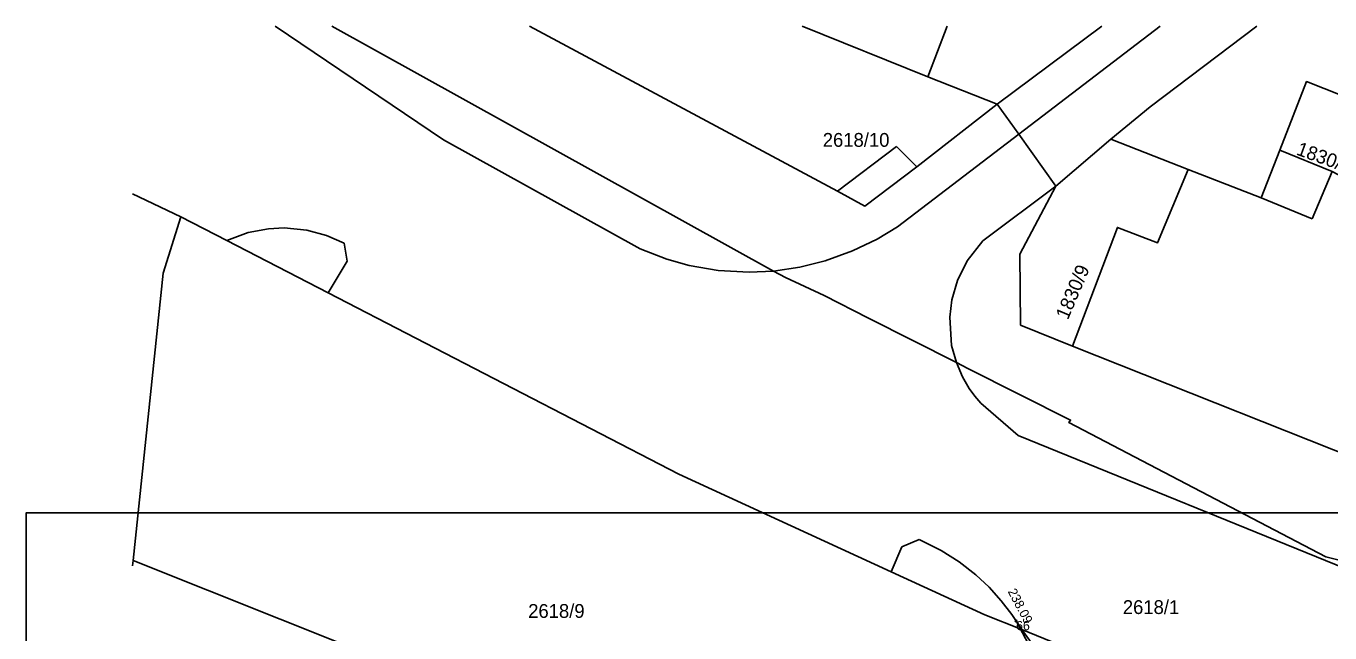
# Model space of a CAD drawing. Extents: x -596309 to -596099, y -1158697 to -1158513.
# Drawn here: x -596309.1 to -596238.2, y -1158545.7 to -1158512.7 of the extents above; entities that cross this region are included whole.
import ezdxf

# ---------------------------------------------------------------- set-up
doc = ezdxf.new("R2010")
doc.units = 0
for name, color, linetype in [('Vrstva 1', 7, 'Continuous'), ('Vrstva 10', 7, 'Continuous'), ('Vrstva 14', 7, 'Continuous'), ('Vrstva 2', 7, 'Continuous'), ('Vrstva 3', 7, 'Continuous'), ('Vrstva 59', 7, 'Continuous'), ('Vrstva 63', 7, 'Continuous')]:
    doc.layers.add(name, color=color, linetype=linetype)

msp = doc.modelspace()

# ---------------------------------------------------------------- linework, layer by layer
at = {"layer": 'Vrstva 1'}
for p, q in [((-596286.36, -1158518.91), (-596295.51, -1158512.73)), ((-596281.683, -1158512.73), (-596264.94, -1158521.71)), ((-596258.974, -1158512.73), (-596260.03, -1158515.48)), ((-596250.58, -1158512.73), (-596256.27, -1158516.97)), ((-596255.09, -1158518.61), (-596247.391, -1158512.73)), ((-596260.63, -1158520.37), (-596256.27, -1158516.97)), ((-596275.68, -1158524.84), (-596286.36, -1158518.91)), ((-596261.68, -1158523.64), (-596255.09, -1158518.61)), ((-596253.07, -1158521.43), (-596250.09, -1158518.88)), ((-596250.09, -1158518.88), (-596245.87, -1158520.53)), ((-596264.94, -1158521.71), (-596261.73, -1158519.27)), ((-596261.73, -1158519.27), (-596260.63, -1158520.37)), ((-596239.14, -1158523.21), (-596238.05, -1158520.63)), ((-596257.04, -1158524.4), (-596253.07, -1158521.43)), ((-596241.91, -1158522.07), (-596239.14, -1158523.21)), ((-596300.64, -1158523.09), (-596301.6, -1158526.16)), ((-596296.98, -1158523.95), (-596295.88, -1158523.74)), ((-596295.88, -1158523.74), (-596295.03, -1158523.7)), ((-596295.03, -1158523.7), (-596293.8, -1158523.82)), ((-596293.8, -1158523.82), (-596292.72, -1158524.11)), ((-596261.68, -1158523.64), (-596262.78, -1158524.31)), ((-596298.15, -1158524.38), (-596296.98, -1158523.95)), ((-596298.15, -1158524.38), (-596292.63, -1158527.23)), ((-596292.72, -1158524.11), (-596291.77, -1158524.52)), ((-596291.77, -1158524.52), (-596291.61, -1158525.51)), ((-596262.78, -1158524.31), (-596264.12, -1158524.95)), ((-596257.89, -1158525.49), (-596257.04, -1158524.4)), ((-596274.22, -1158525.4), (-596275.68, -1158524.84)), ((-596264.12, -1158524.95), (-596265.61, -1158525.49)), ((-596291.61, -1158525.51), (-596292.63, -1158527.23)), ((-596273, -1158525.74), (-596274.22, -1158525.4)), ((-596271.43, -1158526.01), (-596273, -1158525.74)), ((-596269.74, -1158526.11), (-596271.43, -1158526.01)), ((-596268.42, -1158526.04), (-596269.74, -1158526.11)), ((-596266.99, -1158525.83), (-596268.42, -1158526.04)), ((-596265.61, -1158525.49), (-596266.99, -1158525.83)), ((-596258.42, -1158526.55), (-596257.89, -1158525.49)), ((-596301.6, -1158526.16), (-596303.24, -1158541.78)), ((-596258.73, -1158527.61), (-596258.42, -1158526.55)), ((-596258.84, -1158528.54), (-596258.73, -1158527.61)), ((-596258.74, -1158530.09), (-596258.84, -1158528.54)), ((-596255, -1158528.99), (-596252.16, -1158530.12)), ((-596258.47, -1158531.02), (-596258.74, -1158530.09)), ((-596258.15, -1158531.79), (-596258.47, -1158531.02)), ((-596257.78, -1158532.43), (-596258.15, -1158531.79)), ((-596257.48, -1158532.85), (-596257.78, -1158532.43)), ((-596257.15, -1158533.23), (-596257.48, -1158532.85)), ((-596255.12, -1158534.98), (-596257.15, -1158533.23)), ((-596236.76, -1158542.44), (-596255.12, -1158534.98)), ((-596260.5, -1158540.64), (-596261.44, -1158541.03)), ((-596259.31, -1158541.23), (-596260.5, -1158540.64)), ((-596261.44, -1158541.03), (-596262.03, -1158542.38)), ((-596258.32, -1158541.85), (-596259.31, -1158541.23)), ((-596303.24, -1158541.78), (-596303.27, -1158542.067)), ((-596257.42, -1158542.55), (-596258.32, -1158541.85)), ((-596256.7, -1158543.22), (-596257.42, -1158542.55)), ((-596256.04, -1158543.96), (-596256.7, -1158543.22)), ((-596255.46, -1158544.7), (-596256.04, -1158543.96)), ((-596254.92, -1158545.53), (-596255.46, -1158544.7)), ((-596254.92, -1158545.53), (-596253.59, -1158547.37))]:
    msp.add_line(p, q, dxfattribs=at)
for points in [[(-596188.76, -1158560.01), (-596192.69, -1158558.39), (-596195.61, -1158557.19), (-596219.18, -1158547.46), (-596224.47, -1158545.28), (-596230.18, -1158542.92), (-596231.59, -1158542.56), (-596231.75, -1158543.22), (-596238.39, -1158541.58), (-596252.36, -1158534.28), (-596252.27, -1158534.14), (-596257.85, -1158531.33), (-596258.47, -1158531.02), (-596263.25, -1158528.61), (-596265.66, -1158527.37), (-596267.77, -1158526.39), (-596268.42, -1158526.04), (-596292.428, -1158512.73)], [(-596256.27, -1158516.97), (-596260.03, -1158515.48), (-596266.86, -1158512.73)], [(-596250.09, -1158518.88), (-596247.95, -1158517.11), (-596242.147, -1158512.73)], [(-596240.9, -1158519.48), (-596239.44, -1158515.75), (-596234.74, -1158517.6)], [(-596256.27, -1158516.97), (-596255.09, -1158518.61), (-596253.07, -1158521.43)], [(-596240.9, -1158519.48), (-596241.91, -1158522.07), (-596245.87, -1158520.53)], [(-596234.33, -1158521.46), (-596234.57, -1158521.98), (-596237.2, -1158521.09), (-596238.05, -1158520.63), (-596240.9, -1158519.48)], [(-596264.94, -1158521.71), (-596263.45, -1158522.51), (-596260.63, -1158520.37)], [(-596245.87, -1158520.53), (-596247.54, -1158524.5), (-596249.72, -1158523.67), (-596252.16, -1158530.12)], [(-596253.07, -1158521.43), (-596255.03, -1158525.12), (-596255, -1158528.99)], [(-596303.27, -1158521.842), (-596300.64, -1158523.09), (-596298.15, -1158524.38)], [(-596292.63, -1158527.23), (-596273.56, -1158537.08), (-596262.03, -1158542.38), (-596256.93, -1158544.72), (-596254.92, -1158545.53), (-596251.73, -1158546.82), (-596243.57, -1158550.08), (-596194.33, -1158569.02), (-596193.81, -1158569.23), (-596190.04, -1158570.78)], [(-596252.16, -1158530.12), (-596234.09, -1158537.29), (-596233.81, -1158536.7), (-596230.48, -1158538.03)], [(-596221.18, -1158580.18), (-596222, -1158581), (-596223.68, -1158581.67), (-596227, -1158583), (-596228.5, -1158580), (-596228.02, -1158576.15), (-596231.33, -1158574.74), (-596249.42, -1158567.06), (-596252.59, -1158566.74), (-596254.63, -1158566.54), (-596254.08, -1158561.37), (-596258.42, -1158559.64), (-596263.09, -1158557.78), (-596303.24, -1158541.78), (-596303.27, -1158541.768)]]:
    msp.add_lwpolyline(points, dxfattribs=at)
at = {"layer": 'Vrstva 10'}
msp.add_lwpolyline([(-596255.23, -1158545.06), (-596254.2, -1158547.01), (-596253.17, -1158550.76), (-596252.36, -1158555.01), (-596251.99, -1158558.97), (-596251.94, -1158561.36), (-596252.44, -1158566.04), (-596253.24, -1158573.57), (-596254.4, -1158584.31), (-596255.5, -1158594.13), (-596256.77, -1158605.75), (-596257.81, -1158615.11), (-596258.65, -1158622.97), (-596259.56, -1158631.31), (-596260.07, -1158635.97)], dxfattribs=at)
at = {"layer": 'Vrstva 2'}
msp.add_circle((-596255.23, -1158545.06), 0.05, dxfattribs=at)
at = {"layer": 'Vrstva 3'}
msp.add_line((-596255.23, -1158545.06), (-596255.229, -1158545.06), dxfattribs=at)
at = {"layer": 'Vrstva 63'}
msp.add_lwpolyline([(-596309.058, -1158687.689), (-596099.058, -1158687.689), (-596099.058, -1158539.189), (-596309.058, -1158539.189)], close=True, dxfattribs=at)

# ---------------------------------------------------------------- texts
at = {"layer": 'Vrstva 14'}
for s, p in [('2618/10', (-596265.744, -1158519.29)), ('2618/9', (-596281.76, -1158544.89)), ('2618/1', (-596249.43, -1158544.68))]:
    msp.add_text(s, height=0.75, dxfattribs=at).set_placement(p)
for s, rotation, p in [('1830/12', 340, (-596240.045, -1158519.703)), ('1830/9', 67, (-596252.417, -1158528.732))]:
    msp.add_text(s, height=0.75, rotation=rotation, dxfattribs=at).set_placement(p)
at = {"layer": 'Vrstva 2'}
msp.add_text('238.09', height=0.5, rotation=297.84324, dxfattribs=at).set_placement((-596255.701, -1158543.453))
at = {"layer": 'Vrstva 59'}
msp.add_text('66', height=0.5, dxfattribs=at).set_placement((-596255.23, -1158545.56))

doc.saveas('drawing.dxf')
